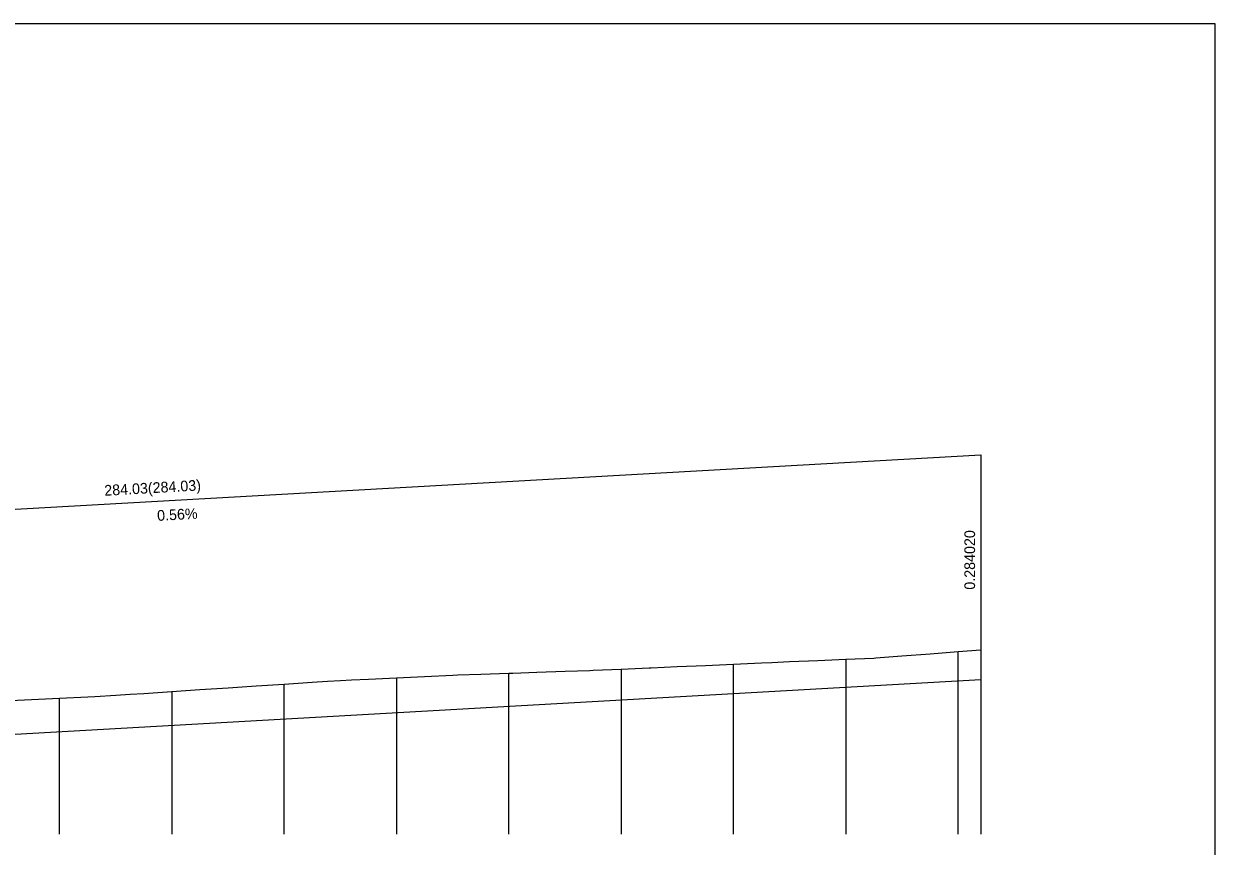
# Model space of a CAD drawing. Extents: x -1257 to 381, y -63 to 234.
# Drawn here: x 168.6 to 380.8, y 87.8 to 234.2 of the extents above; entities that cross this region are included whole.
import ezdxf

# ---------------------------------------------------------------- set-up
doc = ezdxf.new("R2010")
doc.units = 0
for name, color, linetype in [('1', 7, 'Continuous'), ('2', 7, 'Continuous'), ('legenda', 7, 'Continuous')]:
    doc.layers.add(name, color=color, linetype=linetype)

msp = doc.modelspace()

# ---------------------------------------------------------------- linework, layer by layer
msp.add_line((380.78, 234.22), (-39.22, 234.22))
at = {"layer": '1'}
for p, q in [((315, 121.06), (310, 120.84)), ((320, 121.27), (315, 121.06)), ((315, 121.06), (315, 94)), ((320.36, 121.29), (320, 121.27)), ((325, 121.65), (320.36, 121.29)), ((330, 122.04), (325, 121.65)), ((335, 122.43), (330, 122.04)), ((339.02, 122.74), (335, 122.43)), ((335, 94), (335, 122.43)), ((339.02, 122.74), (339.02, 94)), ((339.02, 122.74), (339.02, 122.74)), ((265, 118.92), (260, 118.75)), ((269.4, 119.07), (265, 118.92)), ((270, 119.09), (269.4, 119.07)), ((275, 119.31), (270, 119.09)), ((280, 119.52), (275, 119.31)), ((275, 119.31), (275, 94)), ((280.35, 119.54), (280, 119.52)), ((285, 119.75), (280.35, 119.54)), ((290, 119.96), (285, 119.75)), ((295, 120.19), (290, 119.96)), ((300, 120.41), (295, 120.19)), ((295, 94), (295, 120.19)), ((301.86, 120.49), (300, 120.41)), ((305, 120.63), (301.86, 120.49)), ((310, 120.84), (305, 120.63)), ((220, 116.98), (215, 116.64)), ((222.71, 117.15), (220, 116.98)), ((225, 117.27), (222.71, 117.15)), ((226.99, 117.38), (225, 117.27)), ((230, 117.52), (226.99, 117.38)), ((235, 117.75), (230, 117.52)), ((240, 117.98), (235, 117.75)), ((235, 117.75), (235, 94)), ((245, 118.22), (240, 117.98)), ((245.9, 118.26), (245, 118.22)), ((250, 118.4), (245.9, 118.26)), ((255, 118.58), (250, 118.4)), ((255.72, 118.61), (255, 118.58)), ((255, 94), (255, 118.58)), ((260, 118.75), (255.72, 118.61)), ((185, 114.66), (181.26, 114.42)), ((187.56, 114.82), (185, 114.66)), ((190, 114.98), (187.56, 114.82)), ((195, 115.31), (190, 114.98)), ((200, 115.65), (195, 115.31)), ((195, 115.31), (195, 94)), ((205, 115.98), (200, 115.65)), ((210, 116.31), (205, 115.98)), ((215, 116.64), (210, 116.31)), ((215, 94), (215, 116.64)), ((170, 113.88), (165, 113.63)), ((175, 114.12), (170, 113.88)), ((180, 114.36), (175, 114.12)), ((175, 94), (175, 114.12)), ((181.26, 114.42), (180, 114.36)), ((175, 90), (175, 94)), ((195, 94), (195, 90)), ((215, 90), (215, 94)), ((235, 94), (235, 90)), ((255, 90), (255, 94)), ((275, 94), (275, 90)), ((295, 90), (295, 94)), ((315, 94), (315, 90)), ((335, 90), (335, 94)), ((339.02, 94), (339.02, 90))]:
    msp.add_line(p, q, dxfattribs=at)
at = {"layer": '2'}
for p, q in [((55, 141.5), (339.02, 157.5)), ((339.02, 157.5), (339.02, 117.5)), ((55, 101.5), (339.02, 117.5))]:
    msp.add_line(p, q, dxfattribs=at)
at = {"layer": 'legenda'}
msp.add_line((380.78, -62.78), (380.78, 234.22), dxfattribs=at)

# ---------------------------------------------------------------- texts
at = {"layer": '2'}
for s, rotation, p in [('284.03(284.03)', 3.2242, (183.01, 150.21)), ('  0.56%', 3.2242, (191.01, 145.66)), ('0.284020', 90, (338.02, 133.5))]:
    msp.add_text(s, height=1.9, rotation=rotation, dxfattribs=at).set_placement(p)

doc.saveas('drawing.dxf')
